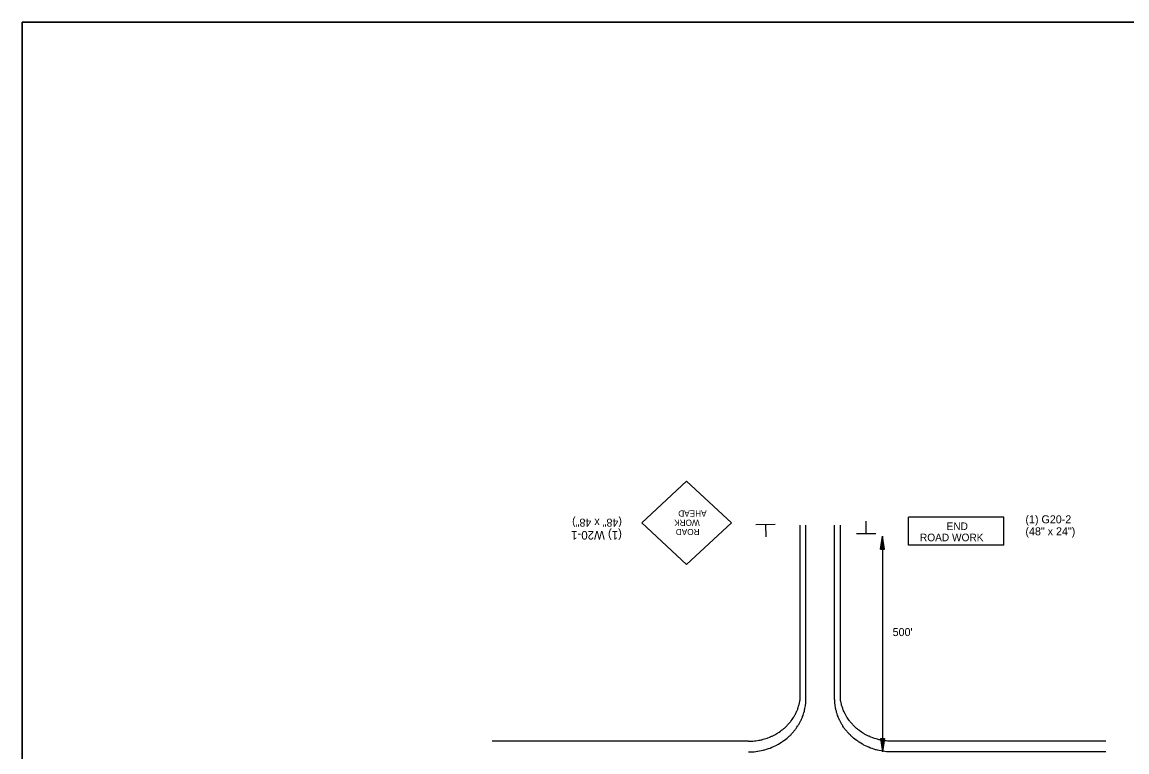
# Model space of a CAD drawing. Extents: x 1416408 to 1429341, y 372694 to 383211.
# Drawn here: x 1426243 to 1427679, y 376199 to 377148 of the extents above; entities that cross this region are included whole.
import ezdxf

# ---------------------------------------------------------------- set-up
doc = ezdxf.new("R2010")
doc.units = 0
for name, color, linetype in [('Default', 7, 'Continuous'), ('DSN_DRFT_Junk-No-Plot', 7, 'Continuous'), ('R_Dimension', 7, 'Continuous'), ('R_MOT', 7, 'Continuous'), ('R_Proposed Road', 7, 'Continuous')]:
    doc.layers.add(name, color=color, linetype=linetype)

msp = doc.modelspace()

# ---------------------------------------------------------------- linework, layer by layer
at = {"layer": 'Default'}
msp.add_lwpolyline([(1426243.1, 377147.9), (1426243.1, 375361.9), (1429003.4, 375361.9), (1429003.4, 377147.9)], close=True, dxfattribs=at)
msp.add_lwpolyline([(1426243.1, 377147.9), (1426243.1, 375361.9), (1429003.4, 375361.9), (1429003.4, 377147.9)], close=True, dxfattribs=at)
at = {"layer": 'DSN_DRFT_Junk-No-Plot'}
msp.add_lwpolyline([(1426243.1, 377147.9), (1429003.4, 377147.9), (1429003.4, 375361.9), (1426243.1, 375361.9)], close=True, dxfattribs=at)
at = {"layer": 'R_Dimension'}
for p, q in [((1427358.7, 376462.5), (1427361.5, 376479.8)), ((1427359.1, 376462.5), (1427361.5, 376477)), ((1427361.5, 376479.8), (1427361.5, 376199.1)), ((1427364.3, 376462.5), (1427361.5, 376479.8)), ((1427363.8, 376462.5), (1427361.5, 376477)), ((1427358.7, 376462.5), (1427364.3, 376462.5)), ((1427359.6, 376462.5), (1427361.5, 376474)), ((1427360.1, 376462.5), (1427361.5, 376471.1)), ((1427360.6, 376462.5), (1427361.5, 376468.1)), ((1427361, 376462.5), (1427361.5, 376465.2)), ((1427363.3, 376462.5), (1427361.5, 376474)), ((1427362.8, 376462.5), (1427361.5, 376471.1)), ((1427362.4, 376462.5), (1427361.5, 376468.1)), ((1427361.9, 376462.5), (1427361.5, 376465.2)), ((1427358.7, 376216.5), (1427361.5, 376199.1)), ((1427358.7, 376216.5), (1427364.3, 376216.5)), ((1427359.1, 376216.5), (1427361.5, 376202)), ((1427359.6, 376216.5), (1427361.5, 376205)), ((1427360.1, 376216.5), (1427361.5, 376207.9)), ((1427360.6, 376216.5), (1427361.5, 376210.8)), ((1427361, 376216.5), (1427361.5, 376213.7)), ((1427364.3, 376216.5), (1427361.5, 376199.1)), ((1427362.4, 376216.5), (1427361.5, 376210.8)), ((1427363.3, 376216.5), (1427361.5, 376205)), ((1427363.8, 376216.5), (1427361.5, 376202)), ((1427362.8, 376216.5), (1427361.5, 376207.9)), ((1427361.9, 376216.5), (1427361.5, 376213.7))]:
    msp.add_line(p, q, dxfattribs=at)
at = {"layer": 'R_MOT'}
for p, q in [((1427048.5, 376496.8), (1427106.8, 376551)), ((1427106.8, 376551), (1427165.2, 376496.8)), ((1427048.5, 376496.8), (1427106.8, 376442.6)), ((1427106.8, 376442.6), (1427165.2, 376496.8)), ((1427196.9, 376494.9), (1427222.1, 376495.3)), ((1427209.5, 376494.8), (1427209.8, 376478.8)), ((1427340.3, 376483.1), (1427340.2, 376499.1)), ((1427519.1, 376504.1), (1427395.2, 376504.1)), ((1427395.2, 376467.9), (1427395.2, 376504.1)), ((1427519.1, 376467.9), (1427519.1, 376504.1)), ((1427352.8, 376482.8), (1427327.6, 376482.7)), ((1427519.1, 376467.9), (1427395.2, 376467.9))]:
    msp.add_line(p, q, dxfattribs=at)
at = {"layer": 'R_Proposed Road'}
for p, q in [((1427254.6, 376427.1), (1427254.6, 376493.8)), ((1427262, 376427.1), (1427262, 376493.8)), ((1427299.3, 376427.1), (1427299.3, 376493.8)), ((1427306.8, 376427.1), (1427306.8, 376493.8))]:
    msp.add_line(p, q, dxfattribs=at)
for points in [[(1427187.4, 376199.1), (1427189.8, 376199.2), (1427192.2, 376199.3), (1427194.6, 376199.4), (1427196.9, 376199.7), (1427199.2, 376200), (1427199.3, 376200), (1427201.7, 376200.4), (1427204, 376200.9), (1427206.3, 376201.4), (1427207.6, 376201.7), (1427208.6, 376202), (1427210.9, 376202.7), (1427213.2, 376203.4), (1427213.4, 376203.5), (1427215.4, 376204.2), (1427217.6, 376205.1), (1427217.9, 376205.2), (1427219.8, 376206), (1427221.8, 376206.9), (1427221.9, 376207), (1427224, 376208), (1427225.2, 376208.7), (1427226.1, 376209.2), (1427228.1, 376210.4), (1427228.2, 376210.4), (1427230.1, 376211.6), (1427230.9, 376212.1), (1427232, 376212.9), (1427233.4, 376213.9), (1427233.9, 376214.3), (1427235.7, 376215.6), (1427235.8, 376215.7), (1427237.6, 376217.1), (1427237.8, 376217.3), (1427239.3, 376218.7), (1427239.8, 376219.1), (1427240.2, 376219.4), (1427241, 376220.2), (1427241.6, 376220.8), (1427242.6, 376221.9), (1427243.3, 376222.5), (1427244.2, 376223.5), (1427244.9, 376224.3), (1427245.7, 376225.2), (1427246.4, 376226), (1427247.2, 376227), (1427247.8, 376227.7), (1427248.6, 376228.8), (1427249.1, 376229.5), (1427249.9, 376230.6), (1427250.3, 376231.2), (1427251.2, 376232.5), (1427251.5, 376232.9), (1427252, 376233.8), (1427252.4, 376234.4), (1427252.6, 376234.7), (1427253.6, 376236.4), (1427253.6, 376236.4), (1427254.5, 376238.1), (1427254.6, 376238.4), (1427255.4, 376239.9), (1427255.6, 376240.4), (1427256.2, 376241.6), (1427256.6, 376242.5), (1427256.9, 376243.3), (1427257.4, 376244.5), (1427257.6, 376245.1), (1427258.2, 376246.6), (1427258.3, 376246.8), (1427258.9, 376248.5), (1427258.9, 376248.7), (1427259.4, 376250.3), (1427259.6, 376250.9), (1427259.9, 376252), (1427260.1, 376253), (1427260.3, 376253.7), (1427260.6, 376255.2), (1427260.7, 376255.5), (1427261, 376257.2), (1427261.1, 376257.4), (1427261.3, 376258.9), (1427261.4, 376259.6), (1427261.5, 376260.7), (1427261.7, 376261.8), (1427261.7, 376262.4), (1427261.9, 376264), (1427261.9, 376264.1), (1427262, 376265.9), (1427262, 376266.3), (1427262, 376267.6), (1427262, 376268.5), (1427262, 376269.3), (1427262, 376271.1), (1427262, 376272.8), (1427262, 376274.5), (1427262, 376276.3), (1427262, 376278), (1427262, 376279.7), (1427262, 376281.5), (1427262, 376283.2), (1427262, 376284.9), (1427262, 376286.7), (1427262, 376288.4), (1427262, 376290.1), (1427262, 376291.9), (1427262, 376293.6), (1427262, 376295.3), (1427262, 376297.1), (1427262, 376298.8), (1427262, 376300.5), (1427262, 376302.3), (1427262, 376304), (1427262, 376305.8), (1427262, 376307.5), (1427262, 376309.2), (1427262, 376311), (1427262, 376312.7), (1427262, 376314.4), (1427262, 376316.2), (1427262, 376317.9), (1427262, 376319.6), (1427262, 376321.4), (1427262, 376323.1), (1427262, 376324.8), (1427262, 376326.6), (1427262, 376328.3), (1427262, 376330), (1427262, 376331.8), (1427262, 376333.5), (1427262, 376335.2), (1427262, 376337), (1427262, 376338.7), (1427262, 376340.4), (1427262, 376342.2), (1427262, 376343.9), (1427262, 376345.6), (1427262, 376347.4), (1427262, 376349.1), (1427262, 376350.8), (1427262, 376352.6), (1427262, 376354.3), (1427262, 376356), (1427262, 376357.8), (1427262, 376359.5), (1427262, 376361.2), (1427262, 376363), (1427262, 376364.7), (1427262, 376366.4), (1427262, 376368.2), (1427262, 376369.9), (1427262, 376371.6), (1427262, 376373.4), (1427262, 376375.1), (1427262, 376376.8), (1427262, 376378.6), (1427262, 376380.3), (1427262, 376382), (1427262, 376383.8), (1427262, 376385.5), (1427262, 376387.2), (1427262, 376389), (1427262, 376390.7), (1427262, 376392.4), (1427262, 376394.2), (1427262, 376395.9), (1427262, 376397.6), (1427262, 376399.4), (1427262, 376401.1), (1427262, 376402.8), (1427262, 376404.6), (1427262, 376406.3), (1427262, 376407.2), (1427262, 376408), (1427262, 376409.8), (1427262, 376411.5), (1427262, 376413.2), (1427262, 376415), (1427262, 376416.7), (1427262, 376418.4), (1427262, 376420.2), (1427262, 376421.9), (1427262, 376423.2), (1427262, 376423.6), (1427262, 376425.4), (1427262, 376427.1)], [(1427187.4, 376213), (1427189.3, 376213), (1427191.2, 376213.1), (1427193.1, 376213.2), (1427195, 376213.4), (1427196.8, 376213.6), (1427196.9, 376213.6), (1427198.8, 376213.9), (1427200.7, 376214.2), (1427202.6, 376214.6), (1427203.7, 376214.8), (1427204.5, 376215), (1427206.3, 376215.5), (1427208.2, 376216), (1427208.3, 376216.1), (1427210, 376216.6), (1427211.8, 376217.2), (1427212.1, 376217.3), (1427213.6, 376217.9), (1427215.3, 376218.5), (1427215.4, 376218.6), (1427217.2, 376219.4), (1427218.1, 376219.8), (1427218.9, 376220.2), (1427220.6, 376221), (1427220.7, 376221.1), (1427222.3, 376221.9), (1427223, 376222.3), (1427224, 376222.9), (1427225.2, 376223.6), (1427225.6, 376223.9), (1427227.2, 376224.9), (1427227.3, 376225), (1427228.8, 376226.1), (1427229, 376226.2), (1427230.4, 376227.2), (1427230.8, 376227.5), (1427231.2, 376227.8), (1427231.9, 376228.4), (1427232.4, 376228.8), (1427233.4, 376229.6), (1427234, 376230.2), (1427234.9, 376230.9), (1427235.5, 376231.5), (1427236.3, 376232.3), (1427236.9, 376232.8), (1427237.6, 376233.6), (1427238.2, 376234.2), (1427239, 376235), (1427239.5, 376235.6), (1427240.3, 376236.5), (1427240.6, 376236.9), (1427241.5, 376238), (1427241.8, 376238.3), (1427242.3, 376239), (1427242.7, 376239.5), (1427242.9, 376239.7), (1427243.9, 376241.1), (1427243.9, 376241.1), (1427244.9, 376242.5), (1427245, 376242.7), (1427245.8, 376243.9), (1427246, 376244.3), (1427246.6, 376245.3), (1427247.1, 376246), (1427247.5, 376246.8), (1427248, 376247.7), (1427248.2, 376248.2), (1427248.9, 376249.5), (1427249, 376249.6), (1427249.7, 376251.1), (1427249.7, 376251.3), (1427250.3, 376252.6), (1427250.5, 376253.1), (1427250.9, 376254), (1427251.3, 376254.9), (1427251.5, 376255.5), (1427251.9, 376256.8), (1427252, 376257), (1427252.5, 376258.5), (1427252.5, 376258.7), (1427252.9, 376260), (1427253.1, 376260.6), (1427253.3, 376261.5), (1427253.5, 376262.5), (1427253.6, 376263.1), (1427253.9, 376264.5), (1427254, 376264.6), (1427254.2, 376266.1), (1427254.3, 376266.5), (1427254.5, 376267.7), (1427254.6, 376268.5), (1427254.6, 376269.3), (1427254.6, 376271.1), (1427254.6, 376272.8), (1427254.6, 376274.5), (1427254.6, 376276.3), (1427254.6, 376278), (1427254.6, 376279.7), (1427254.6, 376281.5), (1427254.6, 376283.2), (1427254.6, 376284.9), (1427254.6, 376286.7), (1427254.6, 376288.4), (1427254.6, 376290.1), (1427254.6, 376291.9), (1427254.6, 376293.6), (1427254.6, 376295.3), (1427254.6, 376297.1), (1427254.6, 376298.8), (1427254.6, 376300.5), (1427254.6, 376302.3), (1427254.6, 376304), (1427254.6, 376305.8), (1427254.6, 376307.5), (1427254.6, 376309.2), (1427254.6, 376311), (1427254.6, 376312.7), (1427254.6, 376314.4), (1427254.6, 376316.2), (1427254.6, 376317.9), (1427254.6, 376319.6), (1427254.6, 376321.4), (1427254.6, 376323.1), (1427254.6, 376324.8), (1427254.6, 376326.6), (1427254.6, 376328.3), (1427254.6, 376330), (1427254.6, 376331.8), (1427254.6, 376333.5), (1427254.6, 376335.2), (1427254.6, 376337), (1427254.6, 376338.7), (1427254.6, 376340.4), (1427254.6, 376342.2), (1427254.6, 376343.9), (1427254.6, 376345.6), (1427254.6, 376347.4), (1427254.6, 376349.1), (1427254.6, 376350.8), (1427254.6, 376352.6), (1427254.6, 376354.3), (1427254.6, 376356), (1427254.6, 376357.8), (1427254.6, 376359.5), (1427254.6, 376361.2), (1427254.6, 376363), (1427254.6, 376364.7), (1427254.6, 376366.4), (1427254.6, 376368.2), (1427254.6, 376369.9), (1427254.6, 376371.6), (1427254.6, 376373.4), (1427254.6, 376375.1), (1427254.6, 376376.8), (1427254.6, 376378.6), (1427254.6, 376380.3), (1427254.6, 376382), (1427254.6, 376383.8), (1427254.6, 376385.5), (1427254.6, 376387.2), (1427254.6, 376389), (1427254.6, 376390.7), (1427254.6, 376392.4), (1427254.6, 376394.2), (1427254.6, 376395.9), (1427254.6, 376397.6), (1427254.6, 376399.4), (1427254.6, 376401.1), (1427254.6, 376402.8), (1427254.6, 376404.6), (1427254.6, 376406.3), (1427254.6, 376407.2), (1427254.6, 376408), (1427254.6, 376409.8), (1427254.6, 376411.5), (1427254.6, 376413.2), (1427254.6, 376415), (1427254.6, 376416.7), (1427254.6, 376418.4), (1427254.6, 376420.2), (1427254.6, 376421.9), (1427254.6, 376423.2), (1427254.6, 376423.6), (1427254.6, 376425.4), (1427254.6, 376427.1)], [(1427373.9, 376199.1), (1427371.5, 376199.2), (1427369.2, 376199.3), (1427366.8, 376199.4), (1427364.4, 376199.7), (1427362.2, 376200), (1427362, 376200), (1427359.7, 376200.4), (1427357.3, 376200.9), (1427355, 376201.4), (1427353.7, 376201.7), (1427352.7, 376202), (1427350.4, 376202.7), (1427348.2, 376203.4), (1427348, 376203.5), (1427345.9, 376204.2), (1427343.7, 376205.1), (1427343.4, 376205.2), (1427341.6, 376206), (1427339.6, 376206.9), (1427339.4, 376207), (1427337.3, 376208), (1427336.2, 376208.7), (1427335.3, 376209.2), (1427333.2, 376210.4), (1427333.2, 376210.4), (1427331.3, 376211.6), (1427330.4, 376212.1), (1427329.3, 376212.9), (1427328, 376213.9), (1427327.4, 376214.3), (1427325.7, 376215.6), (1427325.6, 376215.7), (1427323.8, 376217.1), (1427323.5, 376217.3), (1427322, 376218.7), (1427321.6, 376219.1), (1427321.2, 376219.4), (1427320.3, 376220.2), (1427319.8, 376220.8), (1427318.7, 376221.9), (1427318, 376222.5), (1427317.1, 376223.5), (1427316.5, 376224.3), (1427315.6, 376225.2), (1427315, 376226), (1427314.1, 376227), (1427313.6, 376227.7), (1427312.7, 376228.8), (1427312.2, 376229.5), (1427311.4, 376230.6), (1427311, 376231.2), (1427310.1, 376232.5), (1427309.9, 376232.9), (1427309.3, 376233.8), (1427308.9, 376234.4), (1427308.8, 376234.7), (1427307.8, 376236.4), (1427307.8, 376236.4), (1427306.8, 376238.1), (1427306.7, 376238.4), (1427306, 376239.9), (1427305.7, 376240.4), (1427305.2, 376241.6), (1427304.8, 376242.5), (1427304.4, 376243.3), (1427303.9, 376244.5), (1427303.7, 376245.1), (1427303.1, 376246.6), (1427303.1, 376246.8), (1427302.5, 376248.5), (1427302.4, 376248.7), (1427301.9, 376250.3), (1427301.8, 376250.9), (1427301.5, 376252), (1427301.2, 376253), (1427301, 376253.7), (1427300.7, 376255.2), (1427300.6, 376255.5), (1427300.3, 376257.2), (1427300.3, 376257.4), (1427300, 376258.9), (1427299.9, 376259.6), (1427299.8, 376260.7), (1427299.7, 376261.8), (1427299.6, 376262.4), (1427299.5, 376264), (1427299.5, 376264.1), (1427299.4, 376265.9), (1427299.4, 376266.3), (1427299.3, 376267.6), (1427299.3, 376268.5), (1427299.3, 376269.3), (1427299.3, 376271.1), (1427299.3, 376272.8), (1427299.3, 376274.5), (1427299.3, 376276.3), (1427299.3, 376278), (1427299.3, 376279.7), (1427299.3, 376281.5), (1427299.3, 376283.2), (1427299.3, 376284.9), (1427299.3, 376286.7), (1427299.3, 376288.4), (1427299.3, 376290.1), (1427299.3, 376291.9), (1427299.3, 376293.6), (1427299.3, 376295.3), (1427299.3, 376297.1), (1427299.3, 376298.8), (1427299.3, 376300.5), (1427299.3, 376302.3), (1427299.3, 376304), (1427299.3, 376305.8), (1427299.3, 376307.5), (1427299.3, 376309.2), (1427299.3, 376311), (1427299.3, 376312.7), (1427299.3, 376314.4), (1427299.3, 376316.2), (1427299.3, 376317.9), (1427299.3, 376319.6), (1427299.3, 376321.4), (1427299.3, 376323.1), (1427299.3, 376324.8), (1427299.3, 376326.6), (1427299.3, 376328.3), (1427299.3, 376330), (1427299.3, 376331.8), (1427299.3, 376333.5), (1427299.3, 376335.2), (1427299.3, 376337), (1427299.3, 376338.7), (1427299.3, 376340.4), (1427299.3, 376342.2), (1427299.3, 376343.9), (1427299.3, 376345.6), (1427299.3, 376347.4), (1427299.3, 376349.1), (1427299.3, 376350.8), (1427299.3, 376352.6), (1427299.3, 376354.3), (1427299.3, 376356), (1427299.3, 376357.8), (1427299.3, 376359.5), (1427299.3, 376361.2), (1427299.3, 376363), (1427299.3, 376364.7), (1427299.3, 376366.4), (1427299.3, 376368.2), (1427299.3, 376369.9), (1427299.3, 376371.6), (1427299.3, 376373.4), (1427299.3, 376375.1), (1427299.3, 376376.8), (1427299.3, 376378.6), (1427299.3, 376380.3), (1427299.3, 376382), (1427299.3, 376383.8), (1427299.3, 376385.5), (1427299.3, 376387.2), (1427299.3, 376389), (1427299.3, 376390.7), (1427299.3, 376392.4), (1427299.3, 376394.2), (1427299.3, 376395.9), (1427299.3, 376397.6), (1427299.3, 376399.4), (1427299.3, 376401.1), (1427299.3, 376402.8), (1427299.3, 376404.6), (1427299.3, 376406.3), (1427299.3, 376407.2), (1427299.3, 376408), (1427299.3, 376409.8), (1427299.3, 376411.5), (1427299.3, 376413.2), (1427299.3, 376415), (1427299.3, 376416.7), (1427299.3, 376418.4), (1427299.3, 376420.2), (1427299.3, 376421.9), (1427299.3, 376423.2), (1427299.3, 376423.6), (1427299.3, 376425.4), (1427299.3, 376427.1)], [(1427373.9, 376213), (1427372, 376213), (1427370.1, 376213.1), (1427368.2, 376213.2), (1427366.3, 376213.4), (1427364.5, 376213.6), (1427364.4, 376213.6), (1427362.5, 376213.9), (1427360.6, 376214.2), (1427358.7, 376214.6), (1427357.7, 376214.8), (1427356.9, 376215), (1427355, 376215.5), (1427353.2, 376216), (1427353, 376216.1), (1427351.3, 376216.6), (1427349.5, 376217.2), (1427349.3, 376217.3), (1427347.7, 376217.9), (1427346, 376218.5), (1427345.9, 376218.6), (1427344.2, 376219.4), (1427343.2, 376219.8), (1427342.4, 376220.2), (1427340.7, 376221), (1427340.7, 376221.1), (1427339, 376221.9), (1427338.3, 376222.3), (1427337.4, 376222.9), (1427336.2, 376223.6), (1427335.7, 376223.9), (1427334.2, 376224.9), (1427334.1, 376225), (1427332.5, 376226.1), (1427332.3, 376226.2), (1427331, 376227.2), (1427330.6, 376227.5), (1427330.2, 376227.8), (1427329.4, 376228.4), (1427328.9, 376228.8), (1427327.9, 376229.6), (1427327.3, 376230.2), (1427326.5, 376230.9), (1427325.9, 376231.5), (1427325.1, 376232.3), (1427324.5, 376232.8), (1427323.7, 376233.6), (1427323.1, 376234.2), (1427322.4, 376235), (1427321.9, 376235.6), (1427321.1, 376236.5), (1427320.7, 376236.9), (1427319.8, 376238), (1427319.6, 376238.3), (1427319, 376239), (1427318.6, 376239.5), (1427318.5, 376239.7), (1427317.5, 376241.1), (1427317.5, 376241.1), (1427316.5, 376242.5), (1427316.4, 376242.7), (1427315.6, 376243.9), (1427315.3, 376244.3), (1427314.7, 376245.3), (1427314.3, 376246), (1427313.9, 376246.8), (1427313.3, 376247.7), (1427313.1, 376248.2), (1427312.4, 376249.5), (1427312.4, 376249.6), (1427311.7, 376251.1), (1427311.6, 376251.3), (1427311, 376252.6), (1427310.8, 376253.1), (1427310.4, 376254), (1427310.1, 376254.9), (1427309.9, 376255.5), (1427309.4, 376256.8), (1427309.4, 376257), (1427308.9, 376258.5), (1427308.8, 376258.7), (1427308.4, 376260), (1427308.3, 376260.6), (1427308, 376261.5), (1427307.8, 376262.5), (1427307.7, 376263.1), (1427307.4, 376264.5), (1427307.4, 376264.6), (1427307.1, 376266.1), (1427307.1, 376266.5), (1427306.9, 376267.7), (1427306.8, 376268.5), (1427306.8, 376269.3), (1427306.8, 376271.1), (1427306.8, 376272.8), (1427306.8, 376274.5), (1427306.8, 376276.3), (1427306.8, 376278), (1427306.8, 376279.7), (1427306.8, 376281.5), (1427306.8, 376283.2), (1427306.8, 376284.9), (1427306.8, 376286.7), (1427306.8, 376288.4), (1427306.8, 376290.1), (1427306.8, 376291.9), (1427306.8, 376293.6), (1427306.8, 376295.3), (1427306.8, 376297.1), (1427306.8, 376298.8), (1427306.8, 376300.5), (1427306.8, 376302.3), (1427306.8, 376304), (1427306.8, 376305.8), (1427306.8, 376307.5), (1427306.8, 376309.2), (1427306.8, 376311), (1427306.8, 376312.7), (1427306.8, 376314.4), (1427306.8, 376316.2), (1427306.8, 376317.9), (1427306.8, 376319.6), (1427306.8, 376321.4), (1427306.8, 376323.1), (1427306.8, 376324.8), (1427306.8, 376326.6), (1427306.8, 376328.3), (1427306.8, 376330), (1427306.8, 376331.8), (1427306.8, 376333.5), (1427306.8, 376335.2), (1427306.8, 376337), (1427306.8, 376338.7), (1427306.8, 376340.4), (1427306.8, 376342.2), (1427306.8, 376343.9), (1427306.8, 376345.6), (1427306.8, 376347.4), (1427306.8, 376349.1), (1427306.8, 376350.8), (1427306.8, 376352.6), (1427306.8, 376354.3), (1427306.8, 376356), (1427306.8, 376357.8), (1427306.8, 376359.5), (1427306.8, 376361.2), (1427306.8, 376363), (1427306.8, 376364.7), (1427306.8, 376366.4), (1427306.8, 376368.2), (1427306.8, 376369.9), (1427306.8, 376371.6), (1427306.8, 376373.4), (1427306.8, 376375.1), (1427306.8, 376376.8), (1427306.8, 376378.6), (1427306.8, 376380.3), (1427306.8, 376382), (1427306.8, 376383.8), (1427306.8, 376385.5), (1427306.8, 376387.2), (1427306.8, 376389), (1427306.8, 376390.7), (1427306.8, 376392.4), (1427306.8, 376394.2), (1427306.8, 376395.9), (1427306.8, 376397.6), (1427306.8, 376399.4), (1427306.8, 376401.1), (1427306.8, 376402.8), (1427306.8, 376404.6), (1427306.8, 376406.3), (1427306.8, 376407.2), (1427306.8, 376408), (1427306.8, 376409.8), (1427306.8, 376411.5), (1427306.8, 376413.2), (1427306.8, 376415), (1427306.8, 376416.7), (1427306.8, 376418.4), (1427306.8, 376420.2), (1427306.8, 376421.9), (1427306.8, 376423.2), (1427306.8, 376423.6), (1427306.8, 376425.4), (1427306.8, 376427.1), (1427306.8, 376427.1)], [(1427187.4, 376213), (1427178.1, 376213), (1427159.4, 376213), (1427140.8, 376213), (1427122.1, 376213), (1427103.5, 376213), (1427084.8, 376213), (1427069.9, 376213), (1427066.2, 376213), (1427047.5, 376213), (1427028.8, 376213), (1427010.2, 376213), (1426991.5, 376213), (1426972.9, 376213), (1426954.2, 376213), (1426935.6, 376213), (1426933.3, 376213), (1426916.9, 376213), (1426898.3, 376213), (1426879.6, 376213), (1426861, 376213), (1426854.3, 376213)], [(1427651.6, 376213), (1427644.4, 376213), (1427625.8, 376213), (1427607.1, 376213), (1427588.5, 376213), (1427569.8, 376213), (1427551.2, 376213), (1427532.5, 376213), (1427513.8, 376213), (1427495.2, 376213), (1427479.9, 376213), (1427479.9, 376213), (1427476.5, 376213), (1427457.9, 376213), (1427439.2, 376213), (1427420.6, 376213), (1427401.9, 376213), (1427383.3, 376213), (1427373.9, 376213)], [(1427651.6, 376199.1), (1427644.4, 376199.1), (1427625.8, 376199.1), (1427607.1, 376199.1), (1427588.5, 376199.1), (1427569.8, 376199.1), (1427551.2, 376199.1), (1427532.5, 376199.1), (1427513.8, 376199.1), (1427495.2, 376199.1), (1427479.9, 376199.1), (1427479.9, 376199.1), (1427476.5, 376199.1), (1427457.9, 376199.1), (1427439.2, 376199.1), (1427420.6, 376199.1), (1427401.9, 376199.1), (1427383.3, 376199.1), (1427373.9, 376199.1)]]:
    msp.add_lwpolyline(points, dxfattribs=at)

# ---------------------------------------------------------------- texts
at = {"layer": 'R_Dimension'}
msp.add_text("500'", height=10.4, dxfattribs=at).set_placement((1427374.7, 376349.7))
at = {"layer": 'R_MOT'}
for s, height, rotation, p in [('(48" x 48")', 10.401, 180, (1427022.8, 376502.3)), (' AHEAD ', 7.99, 180.0005, (1427135.8, 376513)), ('WORK', 7.99, 180, (1427123.9, 376501)), ('(1) W20-1', 11.1, 180, (1427022.8, 376486.3)), ('ROAD', 7.99, 180.0004, (1427123.7, 376489))]:
    msp.add_text(s, height=height, rotation=rotation, dxfattribs=at).set_placement(p)
for s, height, p in [('(1) G20-2', 10.4, (1427547.3, 376496.3)), ('END', 9.83, (1427444.8, 376487.6)), ('(48" x 24")', 10.401, (1427547.3, 376480.7)), ('ROAD WORK', 9.83, (1427410.2, 376473))]:
    msp.add_text(s, height=height, dxfattribs=at).set_placement(p)

doc.saveas('drawing.dxf')
